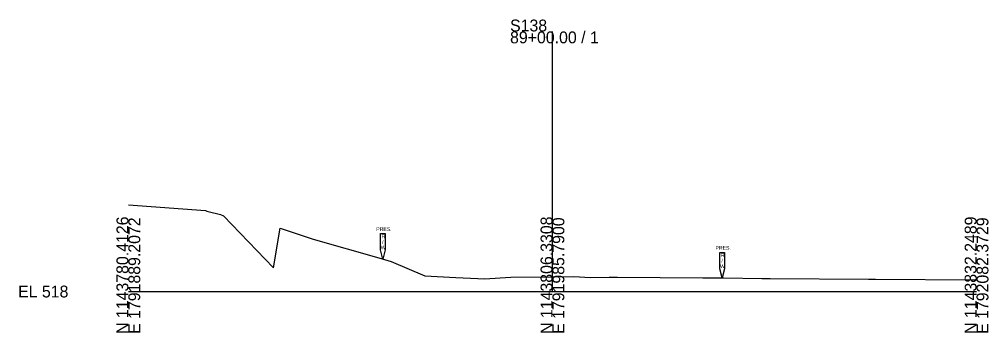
# Model space of a CAD drawing. Extents: x -26 to 1203, y -10 to 19606.
# Drawn here: x -25.7 to 202.8, y 17990.3 to 18064.2 of the extents above; entities that cross this region are included whole.
import ezdxf

# ---------------------------------------------------------------- set-up
doc = ezdxf.new("R2010")
doc.units = 0
for name, color, linetype in [('RD_EX_Driveway', 7, 'Continuous'), ('RD_GPK_XS_Cell', 7, 'Continuous'), ('RD_XS_ExGround', 7, 'Continuous'), ('RD_XS_ExRW', 7, 'Continuous')]:
    doc.layers.add(name, color=color, linetype=linetype)

msp = doc.modelspace()

# ---------------------------------------------------------------- linework, layer by layer
at = {"layer": 'RD_GPK_XS_Cell'}
for p, q in [((100, 18000), (100, 18061.34)), ((0, 18000), (100, 18000)), ((100, 18000), (200, 18000))]:
    msp.add_line(p, q, dxfattribs=at)
at = {"layer": 'RD_XS_ExGround'}
msp.add_lwpolyline([(0, 18020.45), (18.2, 18019.08), (18.51, 18018.93), (18.85, 18018.91), (21.69, 18018.2), (22.4, 18017.89), (34.19, 18005.62), (35.78, 18014.91), (43.59, 18012.34), (59.04, 18007.92), (62, 18007.07), (69.87, 18003.69), (77.22, 18003.31), (82.42, 18003.11), (83.98, 18003.03), (90.19, 18003.37), (100, 18003.49), (105.05, 18003.56), (108.95, 18003.29), (113.36, 18003.35), (115.32, 18003.36), (135.47, 18003.19), (140.35, 18003.2), (149.35, 18003.1), (151.35, 18003.1), (174.54, 18002.94), (176.14, 18002.94), (199.67, 18002.77), (200, 18002.77)], dxfattribs=at)
at = {"layer": 'RD_XS_ExRW'}
for points in [[(59.45, 18013.66), (60.55, 18013.66), (60.55, 18009.83), (60, 18007.65), (59.45, 18009.83)], [(139.45, 18009.22), (140.55, 18009.22), (140.55, 18005.39), (140, 18003.21), (139.45, 18005.39)]]:
    msp.add_lwpolyline(points, close=True, dxfattribs=at)

# ---------------------------------------------------------------- texts
at = {"layer": 'RD_EX_Driveway'}
msp.add_text('519.75', height=0.0975, rotation=90, dxfattribs=at).set_placement((100.1, 18003.49))
at = {"layer": 'RD_GPK_XS_Cell'}
for s, p in [('S138', (90, 18061.34)), ('89+00.00 / 1', (90, 18058.54)), ('EL 518', (-26, 17998.6))]:
    msp.add_text(s, height=2.8, dxfattribs=at).set_placement(p)
for s, p in [('N 1143780.4126', (0, 17990)), ('N 1143806.3308', (100, 17990)), ('N 1143832.2489', (200, 17990)), ('E 1791889.2072', (2.8, 17990)), ('E 1791985.7900', (102.8, 17990)), ('E 1792082.3729', (202.8, 17990))]:
    msp.add_text(s, height=2.8, rotation=90, dxfattribs=at).set_placement(p)
at = {"layer": 'RD_XS_ExRW'}
for s, p in [('PRES.', (58.45, 18014.29)), ('R', (59.71, 18012.57)), ('W', (59.53, 18009.95)), ('/', (59.83, 18011.26)), ('PRES.', (138.45, 18009.85)), ('R', (139.71, 18008.13)), ('W', (139.53, 18005.51)), ('/', (139.83, 18006.82))]:
    msp.add_text(s, height=0.875, dxfattribs=at).set_placement(p)

doc.saveas('drawing.dxf')
